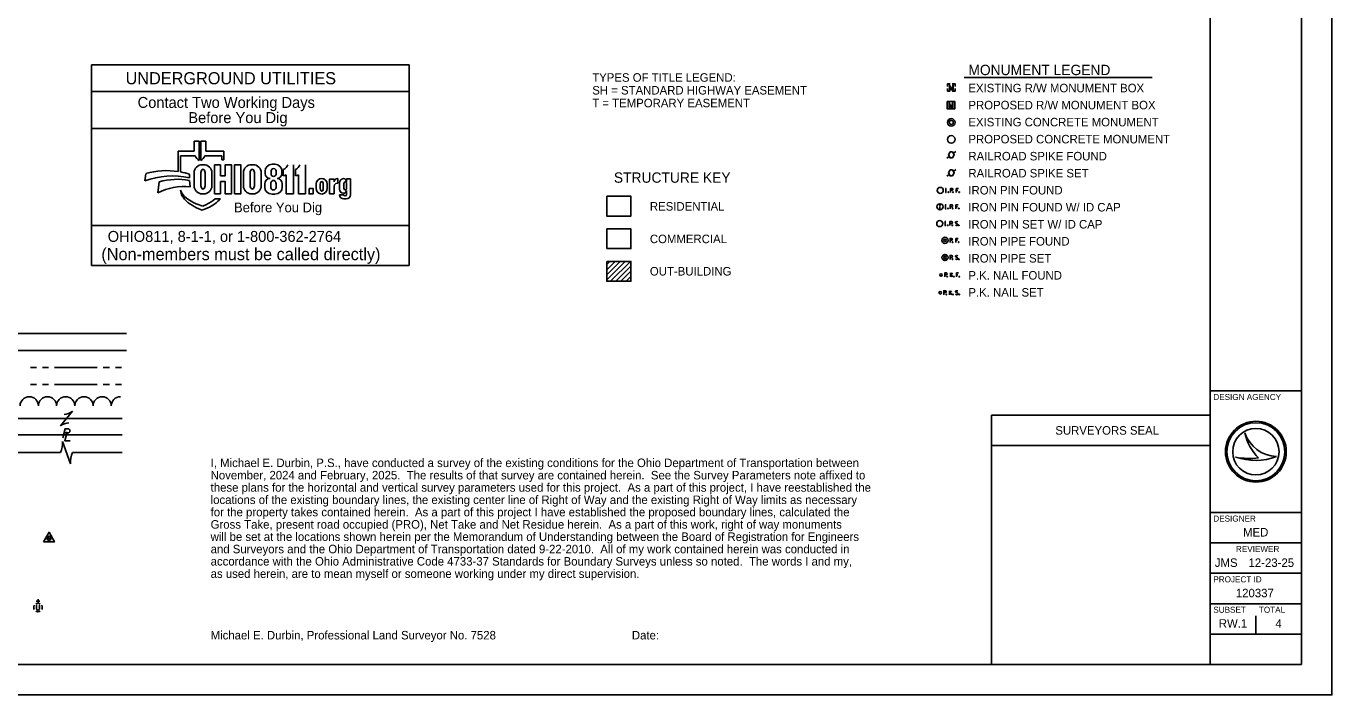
# Model space of a CAD drawing. Extents: x 0 to 34, y 0 to 22.
# Drawn here: x 12.52 to 34, y 0 to 11 of the extents above; entities that cross this region are included whole.
import ezdxf

# ---------------------------------------------------------------- set-up
doc = ezdxf.new("R2010")
doc.units = 0
for name, color, linetype in [('SC_Shading1', 7, 'Continuous'), ('SH_Border', 7, 'Continuous'), ('SH_Cut_Line', 7, 'Continuous'), ('SH_Data', 7, 'Continuous'), ('SH_Text', 7, 'Continuous')]:
    doc.layers.add(name, color=color, linetype=linetype)

msp = doc.modelspace()

# ---------------------------------------------------------------- linework, layer by layer
at = {"layer": 'SC_Shading1'}
msp.add_lwpolyline([(22.071, 7.34), (22.468, 7.34), (22.468, 7.665), (22.071, 7.665)], close=True, dxfattribs=at)
at = {"layer": 'SH_Border'}
for p, q in [((32, 0.5), (32, 21.5)), ((32, 5), (33.5, 5)), ((32, 3), (33.5, 3)), ((32, 2.5), (33.5, 2.5)), ((32, 2), (33.5, 2)), ((32, 1.5), (33.5, 1.5)), ((32, 1), (33.5, 1))]:
    msp.add_line(p, q, dxfattribs=at)
msp.add_lwpolyline([(1.5, 21.5), (33.5, 21.5), (33.5, 0.5), (1.5, 0.5)], close=True, dxfattribs=at)
at = {"layer": 'SH_Cut_Line'}
msp.add_lwpolyline([(0, 0), (34, 0), (34, 22), (0, 22)], close=True, dxfattribs=at)
at = {"layer": 'SH_Data'}
for p, q in [((15.364, 9.108), (15.284, 9.108)), ((15.284, 9.108), (15.284, 8.942)), ((15.364, 8.791), (15.364, 9.108)), ((15.475, 9.108), (15.395, 9.108)), ((15.395, 9.108), (15.395, 8.791)), ((15.475, 8.942), (15.475, 9.108)), ((15.284, 8.942), (15.021, 8.942)), ((15.021, 8.942), (15.021, 8.607)), ((15.059, 8.601), (15.059, 8.865)), ((15.059, 8.865), (15.3, 8.865)), ((15.46, 8.865), (15.738, 8.865)), ((15.773, 8.942), (15.475, 8.942)), ((15.738, 8.865), (15.738, 8.801)), ((15.773, 8.801), (15.773, 8.942)), ((15.441, 8.72), (15.416, 8.72)), ((15.719, 8.719), (15.617, 8.719)), ((15.617, 8.719), (15.617, 8.241)), ((15.738, 8.801), (15.773, 8.801)), ((16.252, 8.72), (16.227, 8.72)), ((16.45, 8.613), (16.45, 8.577)), ((16.549, 8.56), (16.549, 8.618)), ((16.613, 8.727), (16.564, 8.727)), ((16.63, 8.618), (16.63, 8.56)), ((16.727, 8.577), (16.727, 8.613)), ((16.75, 8.539), (16.75, 8.64)), ((16.917, 8.719), (16.917, 8.241)), ((16.95, 8.539), (16.95, 8.64)), ((17.117, 8.719), (17.117, 8.241)), ((14.486, 8.573), (14.472, 8.456)), ((14.707, 8.438), (14.685, 8.258)), ((15.205, 8.505), (15.205, 8.563)), ((15.215, 8.355), (15.206, 8.461)), ((15.283, 8.587), (15.283, 8.375)), ((15.391, 8.392), (15.391, 8.574)), ((15.466, 8.574), (15.466, 8.392)), ((15.575, 8.375), (15.575, 8.587)), ((15.719, 8.241), (15.719, 8.443)), ((16.093, 8.587), (16.093, 8.375)), ((16.202, 8.392), (16.202, 8.574)), ((16.277, 8.574), (16.277, 8.392)), ((16.385, 8.375), (16.385, 8.587)), ((16.444, 8.407), (16.444, 8.356)), ((16.545, 8.347), (16.545, 8.408)), ((16.63, 8.408), (16.63, 8.347)), ((16.733, 8.356), (16.733, 8.407)), ((16.798, 8.241), (16.798, 8.553)), ((16.998, 8.241), (16.998, 8.553)), ((17.29, 8.332), (17.29, 8.4)), ((17.358, 8.331), (17.358, 8.4)), ((17.406, 8.4), (17.406, 8.331)), ((17.473, 8.4), (17.473, 8.332)), ((17.585, 8.484), (17.512, 8.484)), ((17.512, 8.484), (17.512, 8.241)), ((17.585, 8.437), (17.585, 8.484)), ((17.635, 8.418), (17.646, 8.418)), ((17.646, 8.492), (17.64, 8.492)), ((17.646, 8.418), (17.646, 8.492)), ((17.674, 8.319), (17.674, 8.423)), ((17.747, 8.333), (17.747, 8.409)), ((17.789, 8.439), (17.789, 8.486)), ((17.789, 8.486), (17.854, 8.486)), ((17.789, 8.409), (17.789, 8.333)), ((17.854, 8.486), (17.854, 8.227)), ((15.058, 8.301), (15.063, 8.274)), ((15.416, 8.241), (15.441, 8.241)), ((15.617, 8.241), (15.719, 8.241)), ((16.227, 8.241), (16.252, 8.241)), ((16.565, 8.235), (16.612, 8.235)), ((16.917, 8.241), (16.798, 8.241)), ((17.117, 8.241), (16.998, 8.241)), ((17.512, 8.241), (17.585, 8.241)), ((17.585, 8.241), (17.585, 8.368)), ((17.674, 8.227), (17.747, 8.227)), ((17.789, 8.227), (17.789, 8.297)), ((15.423, 8.04), (15.334, 8.071)), ((15.358, 7.994), (15.414, 7.97)), ((15.414, 7.97), (15.508, 8.011)), ((15.484, 8.067), (15.423, 8.04)), ((15.716, 8.161), (15.631, 8.161)), ((15.714, 8.158), (15.716, 8.161)), ((17.784, 8.158), (17.744, 8.158)), ((18.82, 7.063), (13.595, 7.063)), ((32.567, 4.31), (32.567, 4.31)), ((28.4, 4.1), (32, 4.1)), ((32.417, 3.91), (32.417, 3.91)), ((32.75, 4), (32.75, 4)), ((33.087, 3.919), (33.087, 3.919)), ((32.75, 1), (32.75, 1.3))]:
    msp.add_line(p, q, dxfattribs=at)
for points in [[(13.595, 10.363), (18.82, 10.363), (18.82, 9.923), (13.595, 9.923)], [(13.595, 9.923), (18.82, 9.923), (18.82, 9.318), (13.595, 9.318)], [(13.595, 9.318), (18.82, 9.318), (18.82, 7.723), (13.595, 7.723)], [(17.175, 8.331), (17.24, 8.331), (17.24, 8.241), (17.175, 8.241)], [(13.595, 7.723), (18.82, 7.723), (18.82, 7.063), (13.595, 7.063)], [(28.4, 4.6), (32, 4.6), (32, 0.5), (28.4, 0.5)]]:
    msp.add_lwpolyline(points, close=True, dxfattribs=at)
for points in [[(15.719, 8.443), (15.795, 8.443), (15.795, 8.241), (15.896, 8.241), (15.896, 8.719), (15.795, 8.719), (15.795, 8.539), (15.719, 8.539), (15.719, 8.719)], [(15.947, 8.241), (16.05, 8.241), (16.05, 8.719), (15.947, 8.719), (15.947, 8.241)], [(16.531, 8.493), (16.531, 8.493)], [(16.646, 8.493), (16.646, 8.493)]]:
    msp.add_lwpolyline(points, dxfattribs=at)
for radius in [0.5, 0.477, 0.477, 0.382]:
    msp.add_circle((32.75, 4), radius, dxfattribs=at)
for centre, radius, start, end in [((15.436, 8.92), 0.147, 201.9296, 240.7469), ((15.323, 8.92), 0.147, 299.2531, 338.0704), ((14.83, 7.399), 1.224, 81.0007, 106.3144), ((14.83, 7.399), 1.224, 72.1402, 79.2074), ((15.416, 8.587), 0.134, 90, 180), ((15.441, 8.587), 0.134, 0, 90), ((16.227, 8.587), 0.134, 90, 180), ((16.252, 8.587), 0.134, 0, 90), ((16.564, 8.613), 0.114, 90, 180), ((16.613, 8.613), 0.114, 0, 90), ((16.699, 8.763), 0.132, 292.5572, 340.7355), ((16.899, 8.763), 0.132, 292.5572, 340.7355), ((14.924, 7.203), 1.332, 77.8238, 109.8274), ((15.005, 7.386), 1.094, 79.44, 105.8467), ((16.531, 8.407), 0.0865, 90, 180), ((16.534, 8.577), 0.0837, 180, 268.1442), ((16.643, 8.577), 0.0837, 272.2058, 0), ((16.646, 8.407), 0.0865, 0, 90), ((16.738, 8.67), 0.132, 275.1733, 297.0931), ((16.938, 8.67), 0.132, 275.1733, 297.0931), ((17.386, 8.4), 0.0956, 92.5886, 180), ((17.377, 8.4), 0.0956, 0, 87.4114), ((17.64, 8.437), 0.0548, 90, 180), ((17.635, 8.368), 0.0493, 90, 180), ((17.743, 8.423), 0.0686, 92.6865, 180), ((17.737, 8.439), 0.0524, 0, 86.9262), ((15.113, 7.411), 0.95, 83.8248, 116.8021), ((15.338, 8.409), 0.3, 201.0457, 232.5314), ((15.274, 8.31), 0.214, 189.6817, 216.0884), ((15.473, 8.456), 0.461, 216.0884, 235.7167), ((15.626, 8.784), 0.773, 232.5314, 241.794), ((15.416, 8.375), 0.134, 180, 270), ((15.441, 8.375), 0.134, 270, 0), ((16.227, 8.375), 0.134, 180, 270), ((16.252, 8.375), 0.134, 270, 0), ((16.565, 8.356), 0.121, 180, 270), ((16.612, 8.356), 0.121, 270, 0), ((17.386, 8.332), 0.0956, 180, 267.4114), ((17.377, 8.332), 0.0956, 272.5886, 0), ((17.743, 8.319), 0.0692, 180, 265.7132), ((17.744, 8.227), 0.0699, 180, 270), ((17.743, 8.297), 0.0467, 264.7825, 0), ((17.784, 8.227), 0.0699, 270, 0), ((15.722, 8.821), 0.903, 235.7167, 246.2325), ((15.498, 8.547), 0.504, 241.794, 250.9821), ((15.27, 8.56), 0.538, 293.4582, 312.0712), ((15.27, 8.56), 0.599, 293.4582, 317.8286), ((33.116, 4.498), 0.58, 198.9257, 198.9319), ((33.347, 4.47), 0.796, 191.6379, 191.6421), ((33.116, 4.498), 0.58, 198.9319, 267.1657), ((33.347, 4.47), 0.796, 191.6421, 226.0947), ((32.739, 4.87), 1.013, 251.4576, 290.0832), ((32.648, 5.154), 1.266, 259.4964, 259.4995), ((32.739, 4.87), 1.013, 251.4527, 251.4576), ((32.648, 5.154), 1.266, 259.4995, 276.6672)]:
    msp.add_arc(centre, radius, start, end, dxfattribs=at)
for centre, major_axis, ratio, start_param, end_param in [((15.429, 8.574), (0, 0.0723), 0.514403, 4.712389, 7.853982), ((16.239, 8.574), (0, 0.0723), 0.514403, 4.712389, 7.853982), ((16.589, 8.618), (0.0404, 0), 0.969373, 0, 3.141593), ((15.429, 8.392), (0, 0.0723), 0.514403, 1.570796, 4.712389), ((16.239, 8.392), (0, 0.0723), 0.514403, 1.570796, 4.712389), ((16.588, 8.408), (0, 0.0535), 0.794529, 4.712389, 7.853982), ((16.589, 8.56), (0.0404, 0), 0.818453, 3.141593, 6.283185), ((17.382, 8.4), (0, 0.0434), 0.553236, 4.712389, 7.853982), ((17.768, 8.409), (0, 0.0275), 0.777179, 4.712389, 7.853982), ((16.588, 8.347), (0.0425, 0), 0.959837, 3.141593, 6.283185), ((17.382, 8.331), (0, 0.046), 0.522014, 1.570796, 4.712389), ((17.768, 8.333), (0, 0.0275), 0.777179, 1.570796, 4.712389), ((17.768, 8.227), (0.0214, 0), 0.959012, 3.141593, 6.283185)]:
    msp.add_ellipse(centre, major_axis=major_axis, ratio=ratio, start_param=start_param, end_param=end_param, dxfattribs=at)
at = {"layer": 'SH_Text'}
for p, q in [((27.951, 10.157), (31.044, 10.157)), ((27.739, 9.99), (27.739, 9.99)), ((27.734, 9.7), (27.734, 9.7)), ((27.706, 8.858), (27.665, 8.828)), ((27.813, 8.938), (27.773, 8.908)), ((27.813, 8.641), (27.773, 8.611)), ((27.706, 8.561), (27.665, 8.531)), ((27.641, 8.331), (27.657, 8.331)), ((27.641, 8.331), (27.657, 8.331)), ((27.641, 8.264), (27.657, 8.264)), ((27.649, 8.264), (27.649, 8.331)), ((27.726, 8.299), (27.752, 8.299)), ((27.819, 8.264), (27.819, 8.331)), ((27.819, 8.331), (27.858, 8.331)), ((27.819, 8.298), (27.847, 8.298)), ((27.553, 8.033), (27.553, 7.996)), ((27.636, 8.061), (27.653, 8.061)), ((27.636, 8.061), (27.653, 8.061)), ((27.636, 7.995), (27.653, 7.995)), ((27.645, 7.995), (27.645, 8.061)), ((27.721, 8.029), (27.748, 8.029)), ((27.815, 7.995), (27.815, 8.061)), ((27.815, 8.061), (27.853, 8.061)), ((27.815, 8.029), (27.842, 8.029)), ((27.632, 7.785), (27.649, 7.785)), ((27.632, 7.785), (27.649, 7.785)), ((27.64, 7.718), (27.64, 7.785)), ((27.717, 7.753), (27.744, 7.753)), ((27.811, 7.761), (27.842, 7.745)), ((27.632, 7.718), (27.649, 7.718)), ((27.718, 7.477), (27.745, 7.477)), ((27.812, 7.443), (27.812, 7.509)), ((27.812, 7.509), (27.85, 7.509)), ((27.812, 7.477), (27.839, 7.477)), ((22.071, 7.129), (22.072, 7.13)), ((22.071, 7.079), (22.122, 7.13)), ((22.071, 6.994), (22.207, 7.13)), ((22.071, 6.909), (22.291, 7.13)), ((22.071, 6.825), (22.376, 7.13)), ((22.135, 6.804), (22.461, 7.13)), ((27.718, 7.196), (27.745, 7.196)), ((27.813, 7.204), (27.843, 7.188)), ((22.22, 6.804), (22.468, 7.052)), ((22.304, 6.804), (22.468, 6.968)), ((22.389, 6.804), (22.468, 6.883)), ((27.63, 6.909), (27.657, 6.909)), ((27.724, 6.874), (27.724, 6.941)), ((27.724, 6.898), (27.756, 6.941)), ((27.734, 6.912), (27.761, 6.874)), ((27.822, 6.874), (27.822, 6.941)), ((27.822, 6.941), (27.86, 6.941)), ((27.822, 6.908), (27.849, 6.908)), ((22.071, 6.809), (22.075, 6.804)), ((27.616, 6.616), (27.642, 6.616)), ((27.708, 6.581), (27.708, 6.648)), ((27.708, 6.605), (27.74, 6.648)), ((27.719, 6.619), (27.746, 6.581)), ((27.814, 6.624), (27.845, 6.609)), ((10.688, 5.945), (14.172, 5.945)), ((10.688, 5.665), (14.172, 5.665)), ((12.588, 5.385), (12.688, 5.385)), ((12.788, 5.385), (12.888, 5.385)), ((12.988, 5.385), (13.688, 5.385)), ((13.788, 5.385), (13.888, 5.385)), ((13.988, 5.385), (14.088, 5.385)), ((12.588, 5.105), (12.688, 5.105)), ((12.788, 5.105), (12.888, 5.105)), ((12.988, 5.105), (13.688, 5.105)), ((13.788, 5.105), (13.888, 5.105)), ((13.988, 5.105), (14.088, 5.105)), ((12.318, 4.545), (14.1, 4.545)), ((13.083, 4.425), (13.283, 4.665)), ((13.183, 4.545), (13.183, 4.545)), ((13.141, 4.31), (13.206, 4.31)), ((12.318, 4.28), (14.1, 4.28)), ((13.118, 4.169), (13.248, 3.801)), ((13.181, 4.278), (13.181, 4.278)), ((12.318, 3.985), (13.083, 3.985)), ((13.183, 3.985), (13.183, 3.985)), ((13.283, 3.985), (14.1, 3.985)), ((12.746, 1.54), (12.682, 1.54)), ((12.714, 1.508), (12.714, 1.572)), ((12.687, 1.481), (12.687, 1.412)), ((12.714, 1.438), (12.714, 1.438)), ((12.741, 1.481), (12.741, 1.412))]:
    msp.add_line(p, q, dxfattribs=at)
for points in [[(27.677, 10.006), (27.677, 10.053), (27.723, 10.053)], [(27.723, 9.928), (27.677, 9.928), (27.677, 9.974)], [(27.708, 9.948), (27.708, 10.032), (27.739, 9.948), (27.77, 10.032), (27.77, 9.948)], [(27.754, 10.053), (27.802, 10.053), (27.802, 10.006)], [(27.802, 9.974), (27.802, 9.928), (27.754, 9.928)], [(27.672, 9.762), (27.797, 9.762), (27.797, 9.637), (27.672, 9.637), (27.672, 9.762)], [(27.704, 9.658), (27.704, 9.741), (27.734, 9.658), (27.765, 9.741), (27.765, 9.658)], [(27.752, 8.331), (27.726, 8.331), (27.726, 8.264)], [(27.748, 8.061), (27.721, 8.061), (27.721, 7.995)], [(27.744, 7.785), (27.717, 7.785), (27.717, 7.718)], [(27.745, 7.509), (27.718, 7.509), (27.718, 7.443)], [(27.745, 7.228), (27.718, 7.228), (27.718, 7.161)], [(27.657, 6.941), (27.63, 6.941), (27.63, 6.874)], [(27.642, 6.648), (27.616, 6.648), (27.616, 6.581)], [(13.12, 4.23), (13.159, 4.378), (13.211, 4.378)], [(13.194, 4.326), (13.155, 4.179), (13.242, 4.179)]]:
    msp.add_lwpolyline(points, dxfattribs=at)
for points in [[(27.72, 8.933), (27.758, 8.933), (27.787, 8.883), (27.758, 8.833), (27.72, 8.833), (27.691, 8.883)], [(27.72, 8.636), (27.758, 8.636), (27.787, 8.586), (27.758, 8.536), (27.72, 8.536), (27.691, 8.586)], [(22.071, 8.201), (22.468, 8.201), (22.468, 7.875), (22.071, 7.875)], [(22.071, 7.13), (22.468, 7.13), (22.468, 6.804), (22.071, 6.804)], [(12.805, 2.515), (12.985, 2.515), (12.895, 2.676)]]:
    msp.add_lwpolyline(points, close=True, dxfattribs=at)
for centre, radius in [((27.739, 9.417), 0.0625), ((27.739, 9.417), 0.0333), ((27.739, 9.136), 0.0625), ((27.557, 8.297), 0.05), ((27.689, 8.268), 0.00583), ((27.766, 8.268), 0.00583), ((27.867, 8.268), 0.00583), ((27.553, 8.028), 0.05), ((27.553, 8.055), 0.00667), ((27.685, 7.999), 0.00583), ((27.761, 7.999), 0.00583), ((27.863, 7.999), 0.00583), ((27.549, 7.752), 0.05), ((27.635, 7.476), 0.05), ((27.68, 7.723), 0.00583), ((27.757, 7.723), 0.00583), ((27.864, 7.722), 0.00583), ((27.635, 7.476), 0.0206), ((27.758, 7.447), 0.00583), ((27.86, 7.447), 0.00583), ((27.635, 7.194), 0.05), ((27.635, 7.194), 0.0208), ((27.758, 7.166), 0.00583), ((27.865, 7.165), 0.00583), ((27.57, 6.907), 0.0207), ((27.67, 6.878), 0.00583), ((27.78, 6.878), 0.00583), ((27.87, 6.878), 0.00583), ((27.557, 6.614), 0.0206), ((27.656, 6.586), 0.00583), ((27.767, 6.586), 0.00583), ((27.867, 6.586), 0.00583), ((12.895, 2.573), 0.035), ((12.895, 2.573), 0.008)]:
    msp.add_circle(centre, radius, dxfattribs=at)
for centre, radius, start, end in [((27.75, 8.315), 0.0162, 278.8803, 81.1197), ((27.745, 8.045), 0.0162, 278.8803, 81.1197), ((27.741, 7.769), 0.0162, 278.8803, 81.1197), ((27.818, 7.771), 0.0118, 126.2587, 236.3675), ((27.828, 7.75), 0.0349, 61.3463, 118.6537), ((27.832, 7.734), 0.0148, 311.4883, 47.9358), ((27.826, 7.746), 0.0276, 223.6695, 304.3963), ((27.742, 7.493), 0.0162, 278.8803, 81.1197), ((27.742, 7.212), 0.0162, 278.8803, 81.1197), ((27.819, 7.214), 0.0118, 126.2587, 236.3675), ((27.827, 7.189), 0.0276, 223.6695, 304.3963), ((27.829, 7.193), 0.0349, 61.3463, 118.6537), ((27.833, 7.177), 0.0148, 311.4883, 47.9358), ((27.654, 6.925), 0.0162, 278.8803, 81.1197), ((27.64, 6.632), 0.0162, 278.8803, 81.1197), ((27.821, 6.634), 0.0118, 126.2587, 236.3675), ((27.829, 6.609), 0.0276, 223.6695, 304.3963), ((27.831, 6.613), 0.0349, 61.3463, 118.6537), ((27.835, 6.598), 0.0148, 311.4883, 47.9358), ((12.57, 4.755), 0.15, 0.0098, 179.9926), ((12.87, 4.755), 0.15, 0.0098, 179.9926), ((13.17, 4.755), 0.15, 0.0098, 179.9926), ((13.47, 4.755), 0.15, 0.0098, 179.9926), ((13.77, 4.755), 0.15, 0.0098, 179.9926), ((14.07, 4.755), 0.15, 89.9955, 179.9926), ((13.125, 4.88), 0.267, 273.6945, 306.337), ((13.241, 4.21), 0.267, 93.6945, 126.337), ((13.206, 4.344), 0.0345, 270.471, 81.3281), ((12.786, 4.136), 0.334, 332.9422, 5.5848), ((13.58, 3.833), 0.334, 152.9422, 185.5848), ((12.714, 1.438), 0.07, 60.0184, 120.0157), ((12.714, 1.438), 0.07, 150.0184, 209.9816), ((12.714, 1.438), 0.07, 239.9843, 299.9816), ((12.714, 1.425), 0.03, 205.1924, 334.8076), ((12.714, 1.438), 0.07, 330.0184, 29.9816)]:
    msp.add_arc(centre, radius, start, end, dxfattribs=at)

# ---------------------------------------------------------------- texts
at = {"layer": 'SH_Data'}
for s, height, p in [('UNDERGROUND UTILITIES', 0.2, (14.155, 10.043)), ('Contact Two Working Days', 0.18, (14.353, 9.655)), ('Before You Dig', 0.18, (15.187, 9.405)), ('Before You Dig', 0.15972, (15.939, 7.938)), ('OHIO811, 8-1-1, or 1-800-362-2764', 0.18, (13.861, 7.451)), ('(Non-members must be called directly)', 0.2, (13.756, 7.15)), ('DESIGN AGENCY', 0.1, (32.05, 4.85)), ('SURVEYORS SEAL', 0.14, (29.45, 4.28)), ('DESIGNER', 0.1, (32.05, 2.85)), ('MED', 0.14, (32.539, 2.605)), ('REVIEWER', 0.1, (32.422, 2.35)), ('JMS', 0.14, (32.074, 2.105)), ('12-23-25', 0.14, (32.629, 2.105)), ('PROJECT ID', 0.1, (32.05, 1.85)), ('120337', 0.14, (32.42, 1.605)), ('SUBSET', 0.1, (32.05, 1.35)), ('TOTAL', 0.1, (32.8, 1.35)), ('RW.1', 0.14, (32.14, 1.105)), ('4', 0.14, (33.072, 1.105))]:
    msp.add_text(s, height=height, dxfattribs=at).set_placement(p)
at = {"layer": 'SH_Text'}
for s, height, p in [('MONUMENT LEGEND', 0.17, (28.02, 10.194)), ('TYPES OF TITLE LEGEND:', 0.14, (21.832, 10.085)), ('SH = STANDARD HIGHWAY EASEMENT', 0.14, (21.832, 9.875)), ('EXISTING R/W MONUMENT BOX', 0.14, (28.02, 9.911)), ('T = TEMPORARY EASEMENT', 0.14, (21.832, 9.665)), ('PROPOSED R/W MONUMENT BOX', 0.14, (28.02, 9.631)), ('EXISTING CONCRETE MONUMENT', 0.14, (28.02, 9.351)), ('PROPOSED CONCRETE MONUMENT', 0.14, (28.02, 9.071)), ('RAILROAD SPIKE FOUND', 0.14, (28.02, 8.791)), ('STRUCTURE KEY', 0.17, (22.188, 8.424)), ('RAILROAD SPIKE SET', 0.14, (28.02, 8.511)), ('IRON PIN FOUND', 0.14, (28.02, 8.231)), ('RESIDENTIAL', 0.14, (22.78, 7.965)), ('IRON PIN FOUND W/ ID CAP', 0.14, (28.02, 7.951)), ('IRON PIN SET W/ ID CAP', 0.14, (28.02, 7.671)), ('COMMERCIAL', 0.14, (22.78, 7.43)), ('IRON PIPE FOUND', 0.14, (28.02, 7.391)), ('IRON PIPE SET', 0.14, (28.02, 7.111)), ('OUT-BUILDING', 0.14, (22.78, 6.898)), ('P.K. NAIL FOUND', 0.14, (28.02, 6.831)), ('P.K. NAIL SET', 0.14, (28.02, 6.551)), ('I, Michael E. Durbin, P.S., have conducted a survey of the existing conditions for the Ohio Department of Transportation between ', 0.14, (15.554, 3.747)), ('November, 2024 and February, 2025.  The results of that survey are contained herein.  See the Survey Parameters note affixed to  ', 0.14, (15.554, 3.544)), ('these plans for the horizontal and vertical survey parameters used for this project.  As a part of this project, I have reestablished the ', 0.14, (15.554, 3.342)), ('locations of the existing boundary lines, the existing center line of Right of Way and the existing Right of Way limits as necessary  ', 0.14, (15.554, 3.139)), ('for the property takes contained herein.  As a part of this project I have established the proposed boundary lines, calculated the  ', 0.14, (15.554, 2.937)), ('Gross Take, present road occupied (PRO), Net Take and Net Residue herein.  As a part of this work, right of way monuments  ', 0.14, (15.554, 2.734)), ('will be set at the locations shown herein per the Memorandum of Understanding between the Board of Registration for Engineers ', 0.14, (15.554, 2.532)), ('and Surveyors and the Ohio Department of Transportation dated 9-22-2010.  All of my work contained herein was conducted in ', 0.14, (15.554, 2.329)), ('accordance with the Ohio Administrative Code 4733-37 Standards for Boundary Surveys unless so noted.  The words I and my, ', 0.14, (15.554, 2.127)), ('as used herein, are to mean myself or someone working under my direct supervision.', 0.14, (15.554, 1.924)), ('Michael E. Durbin, Professional Land Surveyor No. 7528                                           Date:', 0.14, (15.554, 0.912))]:
    msp.add_text(s, height=height, dxfattribs=at).set_placement(p)

doc.saveas('drawing.dxf')
